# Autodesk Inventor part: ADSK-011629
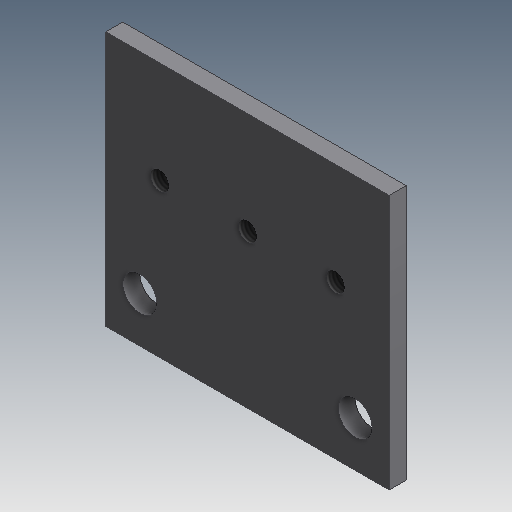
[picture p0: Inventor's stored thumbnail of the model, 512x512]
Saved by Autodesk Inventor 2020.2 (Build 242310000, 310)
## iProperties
Created: 2000-02
Part Number: ADSK-011629
Material: Pearson HRS
Document SubType Name: Modeling
Designer: sspink
Density: 7.83 g/cm^3
Appearance: Métal - Acier
Mass: 407.303 g
Surface Area: 204.477 cm^2
Volume: 52.0182 cm^3
Control State: 0
Master: False
Checked Out: False
Shininess: 0.0
Length Units: 11269
Angle Units: 11279
Time Units: 11290
Mass Units: 11283
Length Display Precision: 3
Angle Display Precision: 2
Compacted: True
Cutlength: 4
Material Desc: FLAT,HRS,0.25 X 3.50
Material_Number: A084334
Dimensions: 90x6x100 mm
Mass: 0,407 kg
VLT_Material: Pearson HRS
Density: 0.0
Volumn: 0.0
Area: 0.0
PropertySet Name: Model Information
Author: sspink
Revision Number: -
Title: ADSK-011629
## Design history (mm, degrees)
sketch "Skizze5"
  geometry: C1 r 4.188 at (12, 16) reference; C2 r 4.188 at (88, 16) reference; 3 further points
  constraints: 2 coincident
hole "Bohrung3" sketch "Skizze5" at (12, 16), (88, 16) diameter "d25" = 12; stored, may be unused: countersink angle "d29" = 82 deg, drill point angle "d31" = 118 deg; dims "d26" = 16.002, "d27" = 9.525, "d28" = 6.35, "d30" = 25.4
derived "ADSK-011628.ipt"
feature "Solide1::ADSK-011628.ipt" dims "d24" = 10
node "Volumenkörper2"
tag "Bezeichnung1"
node "Solide1"
node "Corps solides"
node "Corps surfaciques"
